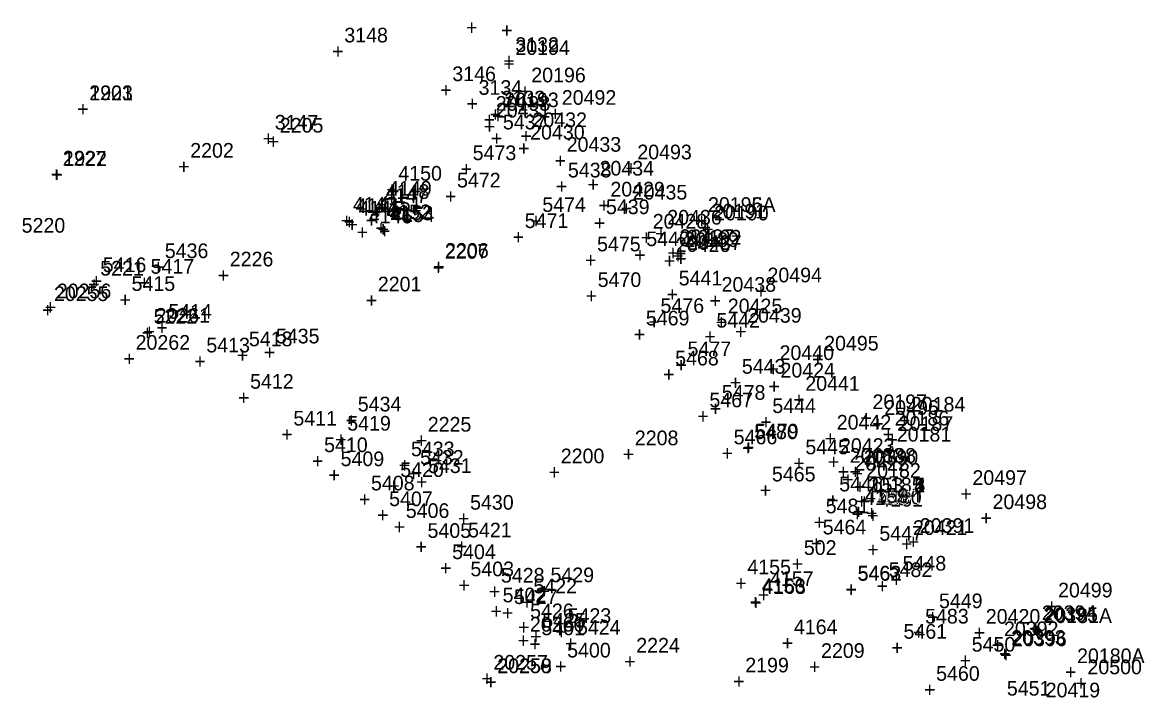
# Model space of a CAD drawing. Extents: x 1036751 to 1042192, y 772604 to 785439.
# Drawn here: x 1041276.6 to 1041468, y 774757.5 to 774872.6 of the extents above; entities that cross this region are included whole.
import ezdxf

# ---------------------------------------------------------------- set-up
doc = ezdxf.new("R2010")
doc.units = 0
for name, color, linetype in [('S_Buildings', 7, 'Continuous'), ('S_Buildings_Attachments', 7, 'Continuous'), ('S_Buildings_SillElevation', 7, 'Continuous'), ('S_Control_Temp_Traverse', 7, 'Continuous'), ('S_Control_Traverse_Point', 7, 'Continuous'), ('S_Curb_Type_2', 7, 'Continuous'), ('S_Ground_LevelString', 7, 'Continuous'), ('S_Property_ConcPad', 7, 'Continuous'), ('S_Property_Walkways', 7, 'Continuous'), ('S_Roadway_Centerline', 7, 'Continuous'), ('S_Roadway_Edge_Pavement', 7, 'Continuous'), ('S_Roadway_Edge_TW', 7, 'Continuous'), ('S_Traffic_Post_Conc', 7, 'Continuous'), ('S_Traffic_Sign_SinglePost', 7, 'Continuous'), ('S_Utilities_GuyWire3', 7, 'Continuous'), ('S_Utilities_Hydrant', 7, 'Continuous'), ('S_Utilities_Pole_Power', 7, 'Continuous'), ('S_Utilities_UG_Water_Gate', 7, 'Continuous'), ('S_Utilities_UG_Water_Line', 7, 'Continuous'), ('S_Utilities_UG_Water_Shutoff', 7, 'Continuous')]:
    doc.layers.add(name, color=color, linetype=linetype)

msp = doc.modelspace()

# ---------------------------------------------------------------- texts
at = {"layer": 'S_Buildings'}
for s, p in [('20196', (1041363.39, 774862.4)), ('+', (1041361.33, 774859.65)), ('20195', (1041393.54, 774840.31)), ('20196A', (1041393.54, 774840.31)), ('+', (1041391.47, 774837.56)), ('+', (1041391.47, 774837.56)), ('20256', (1041282.44, 774825.57)), ('20255', (1041281.96, 774825.1)), ('+', (1041279.9, 774822.35)), ('+', (1041280.38, 774822.82)), ('20197', (1041421.61, 774806.67)), ('+', (1041419.55, 774803.92)), ('20181', (1041425.75, 774801.13)), ('+', (1041423.69, 774798.38)), ('20181A', (1041450.94, 774770.18)), ('+', (1041448.88, 774767.43)), ('20257', (1041356.92, 774762.24)), ('20180A', (1041456.51, 774763.35)), ('+', (1041454.45, 774760.6)), ('+', (1041354.86, 774759.49))]:
    msp.add_text(s, height=2.5, dxfattribs=at).set_placement(p)
at = {"layer": 'S_Buildings_Attachments'}
for s, p in [('20395', (1041450.78, 774770.37)), ('20396', (1041445.45, 774766.24)), ('+', (1041448.72, 774767.62)), ('+', (1041443.39, 774763.49))]:
    msp.add_text(s, height=2.5, dxfattribs=at).set_placement(p)
at = {"layer": 'S_Buildings_SillElevation'}
for s, p in [('20492', (1041368.6, 774858.57)), ('+', (1041366.54, 774855.82)), ('20493', (1041381.48, 774849.27)), ('+', (1041379.42, 774846.52)), ('20494', (1041403.69, 774828.29)), ('+', (1041401.63, 774825.54)), ('20495', (1041413.36, 774816.66)), ('+', (1041411.3, 774813.91)), ('20496', (1041423.62, 774805.69)), ('+', (1041421.56, 774802.94)), ('20497', (1041438.66, 774793.74)), ('+', (1041436.6, 774790.99)), ('20498', (1041442.09, 774789.62)), ('+', (1041440.03, 774786.87)), ('20499', (1041453.27, 774774.56)), ('+', (1041451.21, 774771.81)), ('20500', (1041458.28, 774761.45)), ('+', (1041456.22, 774758.7))]:
    msp.add_text(s, height=2.5, dxfattribs=at).set_placement(p)
at = {"layer": 'S_Control_Temp_Traverse'}
for s, p in [('153', (1041421.3, 774792.46)), ('153', (1041421.3, 774792.46)), ('153', (1041421.3, 774792.46)), ('153', (1041421.3, 774792.46)), ('153_1', (1041421.3, 774792.46)), ('153_3', (1041421.3, 774792.46)), ('153_2', (1041421.3, 774792.46)), ('153_5', (1041421.3, 774792.46)), ('153_4', (1041421.3, 774792.46)), ('+', (1041419.24, 774789.71)), ('+', (1041419.24, 774789.71)), ('+', (1041419.24, 774789.71)), ('+', (1041419.24, 774789.71)), ('+', (1041419.24, 774789.71)), ('+', (1041419.24, 774789.71)), ('+', (1041419.24, 774789.71)), ('+', (1041419.24, 774789.71)), ('+', (1041419.24, 774789.71))]:
    msp.add_text(s, height=2.5, dxfattribs=at).set_placement(p)
at = {"layer": 'S_Control_Traverse_Point'}
for s, p in [('502', (1041409.89, 774781.8)), ('502', (1041409.89, 774781.8)), ('502', (1041409.89, 774781.8)), ('502', (1041409.89, 774781.8)), ('502', (1041409.89, 774781.8)), ('502', (1041409.89, 774781.8)), ('502', (1041409.89, 774781.8)), ('502', (1041409.89, 774781.8)), ('502', (1041409.89, 774781.8)), ('502', (1041409.89, 774781.8)), ('502', (1041409.89, 774781.8)), ('502', (1041409.89, 774781.8)), ('502', (1041409.89, 774781.8)), ('+', (1041407.83, 774779.05)), ('+', (1041407.83, 774779.05)), ('+', (1041407.83, 774779.05)), ('+', (1041407.83, 774779.05)), ('+', (1041407.83, 774779.05)), ('+', (1041407.83, 774779.05)), ('+', (1041407.83, 774779.05)), ('+', (1041407.83, 774779.05)), ('+', (1041407.83, 774779.05)), ('+', (1041407.83, 774779.05)), ('+', (1041407.83, 774779.05)), ('+', (1041407.83, 774779.05)), ('+', (1041407.83, 774779.05))]:
    msp.add_text(s, height=2.5, dxfattribs=at).set_placement(p)
at = {"layer": 'S_Curb_Type_2'}
for s, p in [('5220', (1041276.44, 774836.76)), ('5221', (1041289.85, 774829.45)), ('+', (1041287.79, 774826.71)), ('5222', (1041298.96, 774821.23)), ('+', (1041296.9, 774818.48))]:
    msp.add_text(s, height=2.5, dxfattribs=at).set_placement(p)
at = {"layer": 'S_Ground_LevelString'}
for s, p in [('+', (1041352.25, 774870.52)), ('+', (1041358.24, 774870.03)), ('3146', (1041349.92, 774862.61)), ('3134', (1041354.4, 774860.27)), ('+', (1041347.86, 774859.86)), ('+', (1041352.34, 774857.52)), ('20431', (1041357.35, 774856.39)), ('5437', (1041358.55, 774854.37)), ('2205', (1041320.48, 774853.83)), ('+', (1041355.29, 774853.64)), ('20430', (1041363.2, 774852.65)), ('+', (1041318.42, 774851.08)), ('+', (1041356.49, 774851.62)), ('5473', (1041353.39, 774849.13)), ('+', (1041361.14, 774849.9)), ('5472', (1041350.72, 774844.47)), ('+', (1041351.33, 774846.38)), ('5438', (1041369.64, 774846.18)), ('+', (1041367.58, 774843.43)), ('20429', (1041376.89, 774842.93)), ('+', (1041348.66, 774841.72)), ('5474', (1041365.27, 774840.3)), ('+', (1041374.83, 774840.18)), ('5439', (1041376.13, 774839.92)), ('5471', (1041362.27, 774837.55)), ('+', (1041363.21, 774837.55)), ('+', (1041374.07, 774837.17)), ('20428', (1041384.11, 774837.45)), ('20427', (1041388.67, 774834.83)), ('+', (1041360.21, 774834.8)), ('5475', (1041374.61, 774833.58)), ('+', (1041382.05, 774834.7)), ('5440', (1041383.01, 774834.46)), ('20426', (1041388.06, 774833.47)), ('5436', (1041300.86, 774832.42)), ('2206', (1041348.69, 774832.48)), ('+', (1041380.95, 774831.71)), ('+', (1041386.61, 774832.08)), ('5416', (1041290.28, 774830.03)), ('5417', (1041298.44, 774829.76)), ('+', (1041298.8, 774829.67)), ('+', (1041346.63, 774829.73)), ('+', (1041372.55, 774830.83)), ('+', (1041386, 774830.72)), ('5470', (1041374.72, 774827.5)), ('5441', (1041388.54, 774827.76)), ('+', (1041288.22, 774827.28)), ('5415', (1041295.19, 774826.83)), ('+', (1041296.38, 774827.01)), ('+', (1041293.13, 774824.08)), ('+', (1041372.66, 774824.75)), ('+', (1041386.48, 774825.01)), ('5414', (1041301.47, 774822.08)), ('5476', (1041385.44, 774823.07)), ('20425', (1041396.92, 774823.01)), ('5469', (1041382.94, 774820.95)), ('+', (1041383.38, 774820.32)), ('+', (1041394.86, 774820.26)), ('5442', (1041394.98, 774820.57)), ('+', (1041299.41, 774819.33)), ('5435', (1041319.82, 774817.88)), ('+', (1041380.88, 774818.2)), ('5413', (1041307.95, 774816.34)), ('5418', (1041315.21, 774817.39)), ('5477', (1041390.05, 774815.7)), ('+', (1041392.92, 774817.82)), ('+', (1041313.15, 774814.64)), ('+', (1041317.76, 774815.13)), ('5468', (1041387.94, 774814.12)), ('+', (1041305.89, 774813.59)), ('+', (1041387.99, 774812.95)), ('5443', (1041399.32, 774812.71)), ('20424', (1041405.91, 774812.06)), ('5412', (1041315.42, 774810.15)), ('+', (1041385.88, 774811.37)), ('5478', (1041395.9, 774808.26)), ('+', (1041397.26, 774809.96)), ('+', (1041403.85, 774809.31)), ('+', (1041313.36, 774807.4)), ('5434', (1041333.79, 774806.28)), ('5467', (1041393.78, 774806.98)), ('+', (1041393.84, 774805.51)), ('5444', (1041404.52, 774806)), ('5411', (1041322.8, 774803.87)), ('+', (1041331.73, 774803.53)), ('5419', (1041331.99, 774803)), ('+', (1041391.72, 774804.23)), ('+', (1041402.46, 774803.25)), ('+', (1041320.74, 774801.12)), ('5466', (1041397.92, 774800.67)), ('5480', (1041401.43, 774801.55)), ('5479', (1041401.56, 774801.67)), ('5410', (1041328.04, 774799.33)), ('+', (1041329.93, 774800.25)), ('5433', (1041342.86, 774798.63)), ('+', (1041399.37, 774798.8)), ('+', (1041399.5, 774798.92)), ('5445', (1041410.15, 774798.97)), ('20423', (1041416.06, 774799.2)), ('5409', (1041330.86, 774796.94)), ('5432', (1041344.41, 774797.19)), ('+', (1041395.86, 774797.92)), ('+', (1041325.98, 774796.58)), ('+', (1041340.8, 774795.88)), ('5420', (1041341.03, 774795.1)), ('5431', (1041345.77, 774795.77)), ('+', (1041408.09, 774796.22)), ('+', (1041413.99, 774796.45)), ('20422', (1041418.5, 774796.19)), ('+', (1041328.79, 774794.19)), ('5408', (1041336.04, 774792.81)), ('+', (1041342.35, 774794.44)), ('+', (1041343.71, 774793.02)), ('5465', (1041404.45, 774794.34)), ('5446', (1041415.93, 774792.64)), ('+', (1041416.44, 774793.44)), ('+', (1041338.97, 774792.35)), ('+', (1041402.38, 774791.6)), ('+', (1041333.98, 774790.06)), ('5407', (1041339.14, 774790.12)), ('5430', (1041352.95, 774789.52)), ('5481', (1041413.63, 774788.9)), ('+', (1041413.87, 774789.89)), ('+', (1041337.08, 774787.37)), ('5406', (1041341.98, 774788.11)), ('+', (1041339.92, 774785.36)), ('+', (1041350.89, 774786.77)), ('+', (1041411.57, 774786.15)), ('5464', (1041413.11, 774785.3)), ('20421', (1041428.51, 774785.21)), ('5405', (1041345.69, 774784.71)), ('5421', (1041352.61, 774784.79)), ('5447', (1041422.78, 774784.23)), ('+', (1041343.63, 774781.96)), ('+', (1041350.55, 774782.04)), ('+', (1041411.05, 774782.55)), ('+', (1041426.45, 774782.46)), ('5404', (1041349.89, 774781.08)), ('+', (1041420.72, 774781.48)), ('+', (1041347.83, 774778.33)), ('5403', (1041353.01, 774778.16)), ('5463', (1041419.06, 774777.46)), ('5462', (1041419.08, 774777.39)), ('5482', (1041424.37, 774778.03)), ('5448', (1041426.74, 774779.13)), ('5428', (1041358.21, 774777.08)), ('5429', (1041366.67, 774777.15)), ('+', (1041424.68, 774776.38)), ('+', (1041350.95, 774775.41)), ('+', (1041356.15, 774774.33)), ('5402', (1041358.5, 774773.72)), ('5422', (1041363.76, 774775.25)), ('+', (1041364.61, 774774.4)), ('+', (1041416.99, 774774.71)), ('+', (1041417.02, 774774.64)), ('+', (1041422.31, 774775.28)), ('5427', (1041360.43, 774773.43)), ('+', (1041361.7, 774772.5)), ('5449', (1041432.95, 774772.72)), ('+', (1041356.44, 774770.97)), ('+', (1041358.37, 774770.68)), ('5426', (1041363.19, 774771)), ('5423', (1041369.59, 774770.2)), ('5483', (1041430.58, 774770.1)), ('20420', (1041440.94, 774770.07)), ('+', (1041361.13, 774768.25)), ('5401', (1041365.12, 774768.11)), ('5425', (1041365.26, 774769.4)), ('5424', (1041371.19, 774768.21)), ('+', (1041430.89, 774769.97)), ('+', (1041363.2, 774766.65)), ('+', (1041367.53, 774767.45)), ('5461', (1041426.9, 774767.51)), ('+', (1041428.52, 774767.35)), ('+', (1041438.88, 774767.32)), ('+', (1041363.06, 774765.36)), ('+', (1041369.13, 774765.46)), ('5400', (1041369.51, 774764.31)), ('+', (1041424.84, 774764.76)), ('5450', (1041438.53, 774765.31)), ('+', (1041436.47, 774762.56)), ('+', (1041367.45, 774761.56)), ('5460', (1041432.46, 774760.34)), ('+', (1041430.4, 774757.59)), ('5451', (1041444.53, 774757.81)), ('20419', (1041451.15, 774757.51))]:
    msp.add_text(s, height=2.5, dxfattribs=at).set_placement(p)
at = {"layer": 'S_Property_ConcPad'}
for s, p in [('20194', (1041360.68, 774867.08)), ('+', (1041358.62, 774864.33)), ('20193', (1041358.78, 774858.16)), ('+', (1041356.72, 774855.41)), ('20191', (1041394.17, 774839.18)), ('20190', (1041394.59, 774838.86)), ('20192', (1041389.93, 774834.74)), ('+', (1041392.11, 774836.43)), ('+', (1041392.53, 774836.11)), ('20189', (1041389.51, 774834.32)), ('+', (1041387.45, 774831.57)), ('+', (1041387.87, 774831.99)), ('20261', (1041299.29, 774821.41)), ('+', (1041297.23, 774818.66)), ('20262', (1041295.88, 774816.8)), ('+', (1041293.82, 774814.05)), ('20186', (1041425.39, 774803.87)), ('20187', (1041426.08, 774802.96)), ('+', (1041423.33, 774801.13)), ('+', (1041424.02, 774800.21)), ('20188', (1041419.75, 774797.51)), ('+', (1041417.69, 774794.76)), ('20260', (1041363.15, 774768.72)), ('+', (1041361.08, 774765.97)), ('20259', (1041357.58, 774761.65)), ('20258', (1041357.6, 774761.63)), ('+', (1041355.52, 774758.9)), ('+', (1041355.54, 774758.88))]:
    msp.add_text(s, height=2.5, dxfattribs=at).set_placement(p)
at = {"layer": 'S_Property_Walkways'}
for s, p in [('20390', (1041420.11, 774797.19)), ('+', (1041418.05, 774794.44)), ('20391', (1041429.68, 774785.56)), ('+', (1041427.62, 774782.81)), ('20394', (1041450.5, 774770.69)), ('20392', (1041444.04, 774767.95)), ('20393', (1041445.27, 774766.46)), ('+', (1041448.44, 774767.94)), ('+', (1041441.97, 774765.2)), ('+', (1041443.21, 774763.71))]:
    msp.add_text(s, height=2.5, dxfattribs=at).set_placement(p)
at = {"layer": 'S_Roadway_Centerline'}
for s, p in [('3148', (1041331.49, 774869.21)), ('+', (1041329.42, 774866.46)), ('2203', (1041287.97, 774859.37)), ('1921', (1041287.99, 774859.35)), ('+', (1041285.91, 774856.62)), ('+', (1041285.93, 774856.6)), ('3147', (1041319.63, 774854.34)), ('+', (1041317.57, 774851.59)), ('2202', (1041305.2, 774849.55)), ('+', (1041303.14, 774846.8)), ('2201', (1041337.21, 774826.75)), ('+', (1041335.15, 774824)), ('2200', (1041368.42, 774797.43)), ('+', (1041366.36, 774794.68)), ('2199', (1041399.9, 774761.77)), ('+', (1041397.84, 774759.02))]:
    msp.add_text(s, height=2.5, dxfattribs=at).set_placement(p)
at = {"layer": 'S_Roadway_Edge_Pavement'}
for s, p in [('3132', (1041360.67, 774867.58)), ('+', (1041358.61, 774864.83)), ('3133', (1041358.34, 774858.47)), ('+', (1041356.28, 774855.72))]:
    msp.add_text(s, height=2.5, dxfattribs=at).set_placement(p)
at = {"layer": 'S_Roadway_Edge_TW'}
for s, p in [('2227', (1041283.46, 774848.21)), ('1922', (1041283.57, 774848.15)), ('+', (1041281.4, 774845.46)), ('+', (1041281.51, 774845.4)), ('2226', (1041311.95, 774831.01)), ('2207', (1041348.63, 774832.32)), ('+', (1041346.57, 774829.57)), ('+', (1041309.89, 774828.26)), ('2225', (1041345.73, 774802.83)), ('2208', (1041381.06, 774800.51)), ('+', (1041343.67, 774800.08)), ('+', (1041379, 774797.76)), ('2224', (1041381.3, 774765.15)), ('2209', (1041412.83, 774764.24)), ('+', (1041379.24, 774762.4)), ('+', (1041410.76, 774761.49))]:
    msp.add_text(s, height=2.5, dxfattribs=at).set_placement(p)
at = {"layer": 'S_Traffic_Post_Conc'}
for s, p in [('20432', (1041363.59, 774854.76)), ('+', (1041361.53, 774852.01)), ('20433', (1041369.43, 774850.57)), ('+', (1041367.37, 774847.82)), ('20434', (1041375.04, 774846.5)), ('+', (1041372.98, 774843.75)), ('20435', (1041380.71, 774842.41)), ('+', (1041378.65, 774839.66)), ('20436', (1041386.59, 774838.14)), ('+', (1041384.53, 774835.39)), ('20437', (1041389.99, 774833.83)), ('+', (1041387.93, 774831.08)), ('20438', (1041395.86, 774826.69)), ('+', (1041393.8, 774823.94)), ('20439', (1041400.22, 774821.41)), ('+', (1041398.16, 774818.66)), ('20440', (1041405.75, 774815.04)), ('+', (1041403.69, 774812.29)), ('20441', (1041410.14, 774809.8)), ('+', (1041408.08, 774807.05)), ('20442', (1041415.51, 774803.18)), ('+', (1041413.45, 774800.43))]:
    msp.add_text(s, height=2.5, dxfattribs=at).set_placement(p)
at = {"layer": 'S_Traffic_Sign_SinglePost'}
for s, p in [('20182', (1041420.55, 774794.96)), ('+', (1041418.49, 774792.21))]:
    msp.add_text(s, height=2.5, dxfattribs=at).set_placement(p)
at = {"layer": 'S_Utilities_GuyWire3'}
for s, p in [('20184', (1041428.15, 774806.25)), ('+', (1041426.09, 774803.5))]:
    msp.add_text(s, height=2.5, dxfattribs=at).set_placement(p)
at = {"layer": 'S_Utilities_Hydrant'}
for s, p in [('20185', (1041420.87, 774792.49)), ('+', (1041418.8, 774789.74))]:
    msp.add_text(s, height=2.5, dxfattribs=at).set_placement(p)
at = {"layer": 'S_Utilities_Pole_Power'}
for s, p in [('20198', (1041357.32, 774857.55)), ('+', (1041355.26, 774854.8)), ('20183', (1041417.73, 774797.52)), ('+', (1041415.67, 774794.77))]:
    msp.add_text(s, height=2.5, dxfattribs=at).set_placement(p)
at = {"layer": 'S_Utilities_UG_Water_Gate'}
for s, p in [('4148', (1041338.56, 774842.51)), ('4144', (1041333.43, 774840.12)), ('+', (1041336.5, 774839.76)), ('4153', (1041339.21, 774838.87)), ('+', (1041331.37, 774837.37)), ('+', (1041337.15, 774836.12)), ('4159', (1041420.31, 774790.7)), ('+', (1041418.25, 774787.95))]:
    msp.add_text(s, height=2.5, dxfattribs=at).set_placement(p)
at = {"layer": 'S_Utilities_UG_Water_Line'}
for s, p in [('4150', (1041340.71, 774845.64)), ('+', (1041338.65, 774842.89)), ('4149', (1041338.96, 774843.08)), ('4147', (1041338.27, 774841.85)), ('4143', (1041332.96, 774840.34)), ('4145', (1041333.92, 774839.67)), ('+', (1041336.21, 774839.1)), ('+', (1041336.9, 774840.33)), ('4151', (1041337.22, 774840.38)), ('4152', (1041338.83, 774839.06)), ('4154', (1041339.46, 774838.57)), ('+', (1041330.9, 774837.59)), ('+', (1041335.16, 774837.63)), ('4146', (1041335.66, 774838.35)), ('+', (1041331.86, 774836.92)), ('+', (1041333.6, 774835.6)), ('+', (1041336.77, 774836.31)), ('+', (1041337.4, 774835.82)), ('4158', (1041420.13, 774790.31)), ('+', (1041418.06, 774787.56)), ('4155', (1041400.26, 774778.5)), ('4157', (1041404.12, 774776.51)), ('+', (1041398.2, 774775.75)), ('4156', (1041402.71, 774775.29)), ('4163', (1041402.8, 774775.16)), ('+', (1041400.64, 774772.54)), ('+', (1041400.74, 774772.41)), ('+', (1041402.05, 774773.76)), ('4164', (1041408.2, 774768.28)), ('+', (1041406.13, 774765.53))]:
    msp.add_text(s, height=2.5, dxfattribs=at).set_placement(p)
at = {"layer": 'S_Utilities_UG_Water_Shutoff'}
for s, p in [('4160', (1041422.56, 774790.43)), ('4161', (1041422.76, 774790.04)), ('+', (1041420.5, 774787.68)), ('+', (1041420.7, 774787.29))]:
    msp.add_text(s, height=2.5, dxfattribs=at).set_placement(p)

doc.saveas('drawing.dxf')
